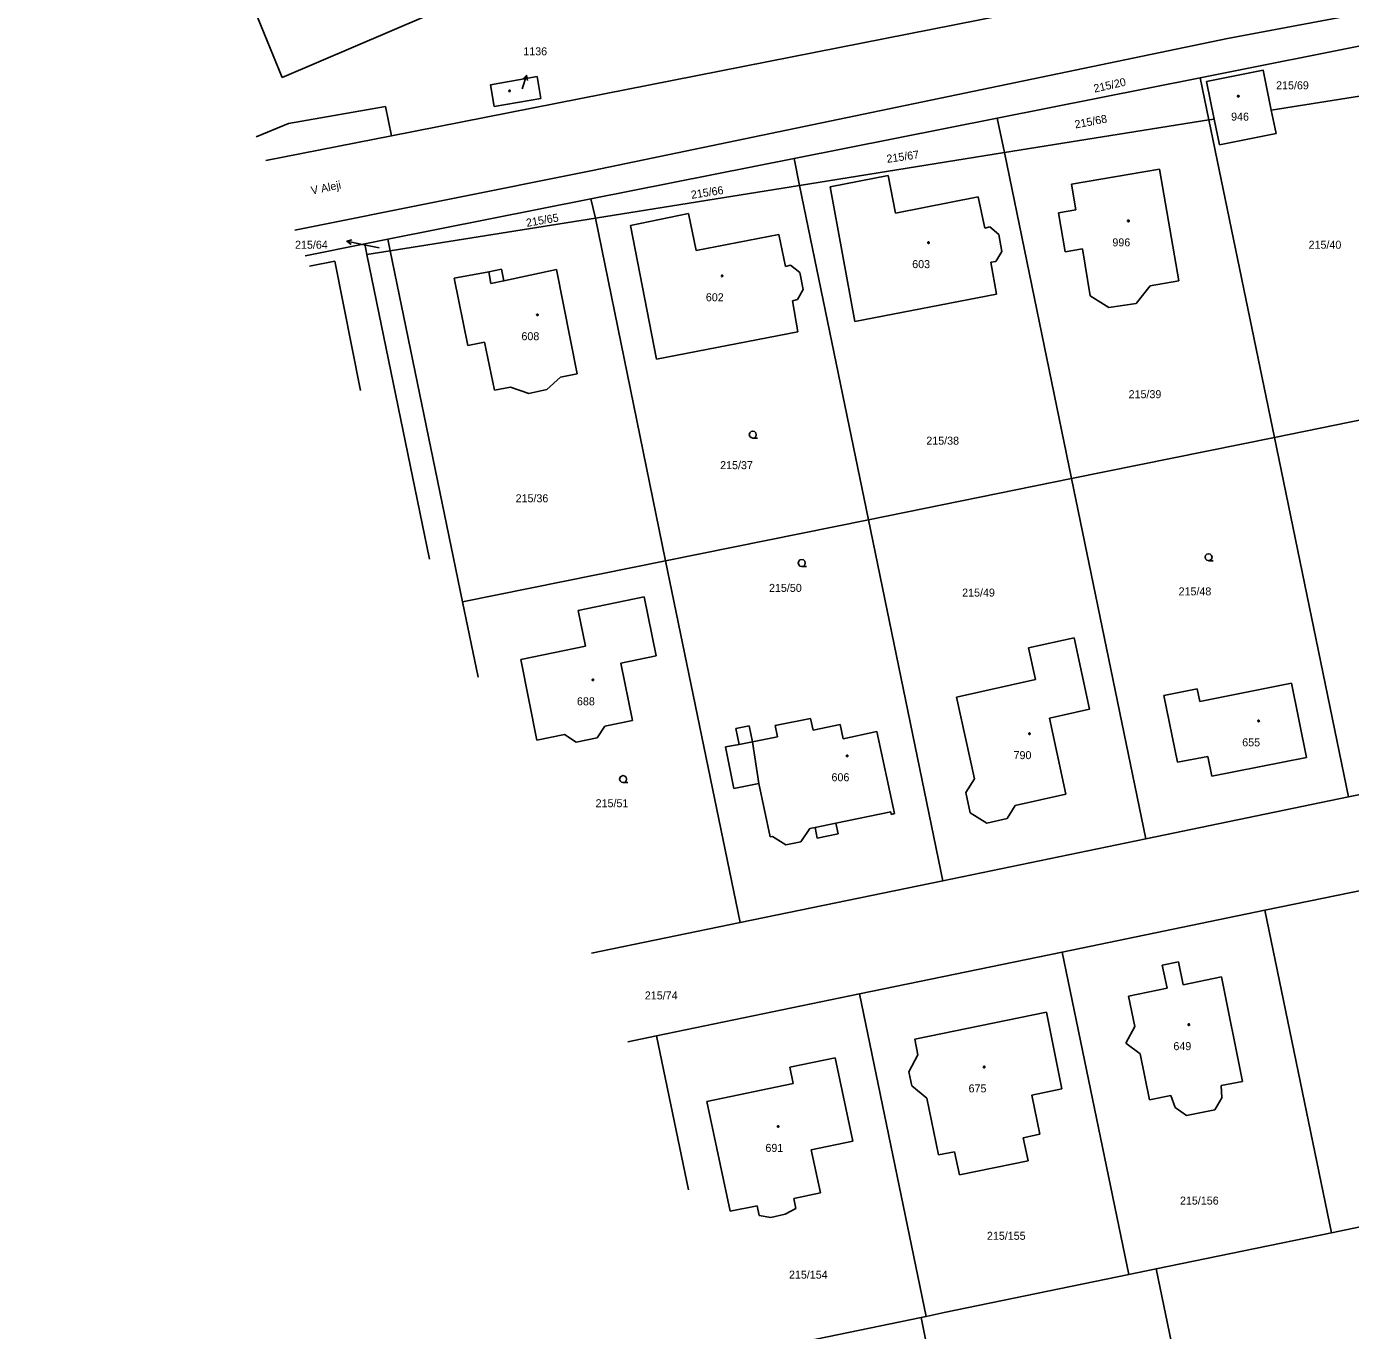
# Model space of a CAD drawing. Extents: x -757994 to -755874, y -1047691 to -1046119.
# Drawn here: x -757810.3 to -757669.7, y -1047577.8 to -1047439.3 of the extents above; entities that cross this region are included whole.
import ezdxf

# ---------------------------------------------------------------- set-up
doc = ezdxf.new("R2010")
doc.units = 0
doc.layers.add('katastrální mapa', color=7, linetype='Continuous')

msp = doc.modelspace()

# ---------------------------------------------------------------- linework, layer by layer
at = {"layer": 'katastrální mapa'}
for p, q in [((-757783.16, -1047444.68), (-757810.32, -1047378.56)), ((-757682.72, -1047440.57), (-757599.86, -1047424.91)), ((-757675.45, -1047431.93), (-757771.54, -1047450.88)), ((-757767.82, -1047438.13), (-757783.16, -1047444.68)), ((-757750.19, -1047454.57), (-757682.72, -1047440.57)), ((-757685.63, -1047444.72), (-757664.05, -1047440.42)), ((-757761.03, -1047445.47), (-757756.06, -1047444.6)), ((-757757.2, -1047444.48), (-757757.65, -1047445.91)), ((-757756.06, -1047444.6), (-757755.68, -1047446.92)), ((-757685.63, -1047444.72), (-757707.2, -1047449.01)), ((-757685.63, -1047444.72), (-757684.71, -1047449.2)), ((-757760.63, -1047447.78), (-757761.03, -1047445.47)), ((-757684.14, -1047449.11), (-757684.95, -1047445.13)), ((-757678.09, -1047448.16), (-757662.94, -1047445.78)), ((-757782.5, -1047449.57), (-757772.19, -1047447.78)), ((-757772.19, -1047447.78), (-757771.54, -1047450.88)), ((-757755.68, -1047446.92), (-757760.63, -1047447.78)), ((-757728.78, -1047453.3), (-757707.2, -1047449.01)), ((-757707.2, -1047449.01), (-757706.44, -1047452.68)), ((-757684.71, -1047449.2), (-757706.44, -1047452.68)), ((-757684.71, -1047449.2), (-757684.14, -1047449.11)), ((-757684.71, -1047449.2), (-757677.75, -1047482.93)), ((-757785.91, -1047450.99), (-757782.5, -1047449.57)), ((-757771.54, -1047450.88), (-757784.88, -1047453.51)), ((-757750.36, -1047457.6), (-757728.78, -1047453.3)), ((-757728.78, -1047453.3), (-757728.19, -1047456.16)), ((-757706.44, -1047452.68), (-757728.19, -1047456.16)), ((-757706.44, -1047452.68), (-757699.32, -1047487.3)), ((-757781.83, -1047460.92), (-757750.19, -1047454.57)), ((-757699.3, -1047456.03), (-757689.94, -1047454.42)), ((-757689.94, -1047454.42), (-757687.9, -1047466.29)), ((-757728.19, -1047456.16), (-757749.88, -1047459.64)), ((-757720.88, -1047491.68), (-757728.19, -1047456.16)), ((-757724.96, -1047456.32), (-757718.77, -1047455.12)), ((-757722.31, -1047470.62), (-757724.96, -1047456.32)), ((-757718.77, -1047455.12), (-757718.01, -1047459.1)), ((-757698.85, -1047458.76), (-757699.3, -1047456.03)), ((-757771.94, -1047461.89), (-757750.36, -1047457.6)), ((-757750.36, -1047457.6), (-757749.88, -1047459.64)), ((-757718.01, -1047459.1), (-757709.22, -1047457.37)), ((-757709.22, -1047457.37), (-757708.53, -1047460.69)), ((-757746.16, -1047460.41), (-757739.98, -1047459.16)), ((-757739.98, -1047459.16), (-757739.18, -1047463.08)), ((-757700.68, -1047459.07), (-757698.85, -1047458.76)), ((-757699.97, -1047463.21), (-757700.68, -1047459.07)), ((-757749.88, -1047459.64), (-757771.68, -1047463.13)), ((-757749.88, -1047459.64), (-757742.44, -1047496.05)), ((-757743.4, -1047474.62), (-757746.16, -1047460.41)), ((-757708.53, -1047460.69), (-757707.97, -1047460.57)), ((-757707.97, -1047460.57), (-757707.01, -1047461.36)), ((-757774.39, -1047462.38), (-757771.94, -1047461.89)), ((-757771.94, -1047461.89), (-757771.68, -1047463.13)), ((-757739.18, -1047463.08), (-757730.38, -1047461.39)), ((-757730.38, -1047461.39), (-757729.7, -1047464.76)), ((-757707.01, -1047461.36), (-757706.7, -1047463.18)), ((-757774.39, -1047462.38), (-757780.72, -1047463.64)), ((-757776.28, -1047462.09), (-757774.81, -1047462.4)), ((-757772.84, -1047462.81), (-757774.81, -1047462.4)), ((-757774.39, -1047462.38), (-757774.15, -1047463.52)), ((-757774.15, -1047463.52), (-757771.68, -1047463.13)), ((-757771.68, -1047463.13), (-757764, -1047500.42)), ((-757706.7, -1047463.18), (-757707.34, -1047464.23)), ((-757698.14, -1047462.91), (-757699.97, -1047463.21)), ((-757697.31, -1047467.9), (-757698.14, -1047462.91)), ((-757780.27, -1047464.74), (-757777.56, -1047464.21)), ((-757777.56, -1047464.21), (-757774.84, -1047477.95)), ((-757767.49, -1047495.89), (-757774.15, -1047463.52)), ((-757729.7, -1047464.76), (-757729.15, -1047464.64)), ((-757729.15, -1047464.64), (-757728.18, -1047465.42)), ((-757707.34, -1047464.23), (-757707.89, -1047464.33)), ((-757707.89, -1047464.33), (-757707.26, -1047467.71)), ((-757761.22, -1047465.33), (-757764.87, -1047466.03)), ((-757764.87, -1047466.03), (-757763.42, -1047473.16)), ((-757759.86, -1047465.07), (-757761.22, -1047465.33)), ((-757761.22, -1047465.33), (-757760.98, -1047466.57)), ((-757759.62, -1047466.31), (-757759.86, -1047465.07)), ((-757754, -1047465.09), (-757759.62, -1047466.31)), ((-757751.81, -1047476.19), (-757754, -1047465.09)), ((-757728.18, -1047465.42), (-757727.82, -1047467.21)), ((-757760.98, -1047466.57), (-757759.62, -1047466.31)), ((-757727.82, -1047467.21), (-757728.4, -1047468.28)), ((-757690.94, -1047466.82), (-757692.43, -1047468.7)), ((-757687.9, -1047466.29), (-757690.94, -1047466.82)), ((-757728.4, -1047468.28), (-757728.96, -1047468.41)), ((-757728.96, -1047468.41), (-757728.37, -1047471.73)), ((-757707.26, -1047467.71), (-757722.31, -1047470.62)), ((-757695.35, -1047469.12), (-757697.31, -1047467.9)), ((-757692.43, -1047468.7), (-757695.35, -1047469.12)), ((-757728.37, -1047471.73), (-757743.4, -1047474.62)), ((-757763.42, -1047473.16), (-757761.65, -1047472.8)), ((-757761.65, -1047472.8), (-757760.61, -1047477.92)), ((-757755.03, -1047477.84), (-757753.58, -1047476.55)), ((-757753.58, -1047476.55), (-757751.81, -1047476.19)), ((-757760.61, -1047477.92), (-757758.89, -1047477.6)), ((-757758.89, -1047477.6), (-757756.96, -1047478.26)), ((-757756.96, -1047478.26), (-757755.03, -1047477.84)), ((-757656.19, -1047478.56), (-757677.75, -1047482.93)), ((-757677.75, -1047482.93), (-757699.32, -1047487.3)), ((-757677.75, -1047482.93), (-757669.87, -1047521.14)), ((-757699.32, -1047487.3), (-757720.88, -1047491.68)), ((-757691.42, -1047525.59), (-757699.32, -1047487.3)), ((-757742.44, -1047496.05), (-757720.88, -1047491.68)), ((-757720.88, -1047491.68), (-757712.96, -1047530.04)), ((-757742.44, -1047496.05), (-757764, -1047500.42)), ((-757734.51, -1047534.49), (-757742.44, -1047496.05)), ((-757751.72, -1047501.33), (-757744.71, -1047499.89)), ((-757744.71, -1047499.89), (-757743.42, -1047506.16)), ((-757764, -1047500.42), (-757762.35, -1047508.4)), ((-757750.93, -1047505.1), (-757751.72, -1047501.33)), ((-757757.82, -1047506.53), (-757750.93, -1047505.1)), ((-757699.02, -1047504.22), (-757703.87, -1047505.29)), ((-757703.87, -1047505.29), (-757703.14, -1047508.65)), ((-757697.38, -1047511.8), (-757699.02, -1047504.22)), ((-757756.1, -1047515.09), (-757757.82, -1047506.53)), ((-757743.42, -1047506.16), (-757747.19, -1047506.93)), ((-757747.19, -1047506.93), (-757745.94, -1047513.01)), ((-757703.14, -1047508.65), (-757711.51, -1047510.53)), ((-757689.51, -1047510.35), (-757685.97, -1047509.64)), ((-757685.97, -1047509.64), (-757685.69, -1047511.01)), ((-757685.69, -1047511.01), (-757675.92, -1047509.05)), ((-757675.92, -1047509.05), (-757674.33, -1047516.94)), ((-757711.51, -1047510.53), (-757709.61, -1047519.22)), ((-757688.05, -1047517.45), (-757689.51, -1047510.35)), ((-757701.66, -1047512.75), (-757697.38, -1047511.8)), ((-757748.87, -1047513.61), (-757749.69, -1047514.85)), ((-757745.94, -1047513.01), (-757748.87, -1047513.61)), ((-757734.95, -1047513.86), (-757733.54, -1047513.57)), ((-757734.6, -1047515.57), (-757734.95, -1047513.86)), ((-757733.54, -1047513.57), (-757733.2, -1047515.29)), ((-757730.79, -1047513.53), (-757727.02, -1047512.8)), ((-757730.54, -1047514.75), (-757730.79, -1047513.53)), ((-757727.02, -1047512.8), (-757726.74, -1047514.05)), ((-757726.74, -1047514.05), (-757723.88, -1047513.44)), ((-757723.88, -1047513.44), (-757723.56, -1047514.95)), ((-757699.91, -1047520.83), (-757701.66, -1047512.75)), ((-757753.18, -1047514.5), (-757756.1, -1047515.09)), ((-757751.94, -1047515.32), (-757753.18, -1047514.5)), ((-757749.69, -1047514.85), (-757751.94, -1047515.32)), ((-757734.6, -1047515.57), (-757733.2, -1047515.29)), ((-757733.2, -1047515.29), (-757730.54, -1047514.75)), ((-757733.2, -1047515.29), (-757732.53, -1047519.71)), ((-757723.56, -1047514.95), (-757719.99, -1047514.18)), ((-757719.99, -1047514.18), (-757718.12, -1047522.89)), ((-757736.05, -1047515.81), (-757734.6, -1047515.57)), ((-757736.05, -1047515.81), (-757735.16, -1047520.23)), ((-757684.84, -1047516.84), (-757688.05, -1047517.45)), ((-757684.39, -1047518.92), (-757684.84, -1047516.84)), ((-757669.87, -1047521.14), (-757648.32, -1047516.69)), ((-757674.33, -1047516.94), (-757684.39, -1047518.92)), ((-757709.61, -1047519.22), (-757710.52, -1047520.66)), ((-757735.16, -1047520.23), (-757732.53, -1047519.71)), ((-757732.53, -1047519.71), (-757731.32, -1047525.39)), ((-757710.52, -1047520.66), (-757710.07, -1047522.83)), ((-757705.28, -1047522.03), (-757699.91, -1047520.83)), ((-757706.14, -1047523.44), (-757705.28, -1047522.03)), ((-757669.87, -1047521.14), (-757691.42, -1047525.59)), ((-757718.51, -1047522.71), (-757724.34, -1047523.92)), ((-757718.45, -1047522.99), (-757718.51, -1047522.71)), ((-757718.12, -1047522.89), (-757718.45, -1047522.99)), ((-757710.07, -1047522.83), (-757708.31, -1047523.92)), ((-757708.31, -1047523.92), (-757706.14, -1047523.44)), ((-757728.05, -1047525.92), (-757727.12, -1047524.5)), ((-757727.12, -1047524.5), (-757726.54, -1047524.38)), ((-757726.54, -1047524.38), (-757724.34, -1047523.92)), ((-757726.54, -1047524.38), (-757726.31, -1047525.5)), ((-757726.31, -1047525.5), (-757724.11, -1047525.04)), ((-757724.11, -1047525.04), (-757724.34, -1047523.92)), ((-757731.32, -1047525.39), (-757731.07, -1047525.35)), ((-757731.07, -1047525.35), (-757729.67, -1047526.24)), ((-757729.67, -1047526.24), (-757728.05, -1047525.92)), ((-757712.96, -1047530.04), (-757691.42, -1047525.59)), ((-757678.75, -1047533.17), (-757657.2, -1047528.72)), ((-757712.96, -1047530.04), (-757734.51, -1047534.49)), ((-757700.29, -1047537.62), (-757678.75, -1047533.17)), ((-757678.75, -1047533.17), (-757671.67, -1047567.44)), ((-757750.31, -1047537.75), (-757734.51, -1047534.49)), ((-757721.84, -1047542.07), (-757700.29, -1047537.62)), ((-757700.29, -1047537.62), (-757693.21, -1047571.89)), ((-757689.67, -1047539.01), (-757687.95, -1047538.65)), ((-757689.16, -1047541.46), (-757689.67, -1047539.01)), ((-757687.95, -1047538.65), (-757687.44, -1047541.1)), ((-757687.44, -1047541.1), (-757683.38, -1047540.25)), ((-757683.38, -1047540.25), (-757681.15, -1047551.38)), ((-757743.38, -1047546.51), (-757721.84, -1047542.07)), ((-757721.84, -1047542.07), (-757714.76, -1047576.34)), ((-757693.24, -1047542.31), (-757689.16, -1047541.46)), ((-757692.59, -1047545.52), (-757693.24, -1047542.31)), ((-757715.96, -1047546.88), (-757701.95, -1047544.02)), ((-757701.95, -1047544.02), (-757700.32, -1047552.16)), ((-757693.52, -1047547.31), (-757692.59, -1047545.52)), ((-757746.45, -1047547.14), (-757743.38, -1047546.51)), ((-757743.38, -1047546.51), (-757740, -1047562.87)), ((-757715.62, -1047548.54), (-757715.96, -1047546.88)), ((-757692, -1047548.44), (-757693.52, -1047547.31)), ((-757729.23, -1047549.85), (-757724.4, -1047548.86)), ((-757724.4, -1047548.86), (-757722.55, -1047557.7)), ((-757716.58, -1047550.35), (-757715.62, -1047548.54)), ((-757691.01, -1047553.33), (-757692, -1047548.44)), ((-757728.88, -1047551.59), (-757729.23, -1047549.85)), ((-757716.27, -1047551.84), (-757716.58, -1047550.35)), ((-757738.04, -1047553.51), (-757728.88, -1047551.59)), ((-757714.68, -1047553.13), (-757716.27, -1047551.84)), ((-757681.15, -1047551.38), (-757683.41, -1047551.81)), ((-757683.41, -1047551.81), (-757683.35, -1047553.12)), ((-757713.45, -1047559.18), (-757714.68, -1047553.13)), ((-757700.32, -1047552.16), (-757703.52, -1047552.81)), ((-757703.52, -1047552.81), (-757702.67, -1047556.98)), ((-757688.76, -1047552.87), (-757691.01, -1047553.33)), ((-757688.3, -1047554.12), (-757688.76, -1047552.87)), ((-757683.35, -1047553.12), (-757684.09, -1047554.38)), ((-757735.56, -1047565.15), (-757738.04, -1047553.51)), ((-757687.08, -1047554.98), (-757688.3, -1047554.12)), ((-757684.09, -1047554.38), (-757687.08, -1047554.98)), ((-757702.67, -1047556.98), (-757704.43, -1047557.34)), ((-757704.43, -1047557.34), (-757703.92, -1047559.81)), ((-757722.55, -1047557.7), (-757726.96, -1047558.62)), ((-757726.96, -1047558.62), (-757725.97, -1047563.19)), ((-757711.72, -1047558.83), (-757713.45, -1047559.18)), ((-757711.21, -1047561.3), (-757711.72, -1047558.83)), ((-757703.92, -1047559.81), (-757711.21, -1047561.3)), ((-757725.97, -1047563.19), (-757728.82, -1047563.81)), ((-757732.7, -1047564.58), (-757735.56, -1047565.15)), ((-757732.5, -1047565.62), (-757732.7, -1047564.58)), ((-757728.82, -1047563.81), (-757728.59, -1047564.86)), ((-757731.23, -1047565.83), (-757732.5, -1047565.62)), ((-757729.74, -1047565.48), (-757731.23, -1047565.83)), ((-757728.59, -1047564.86), (-757729.74, -1047565.48)), ((-757690.32, -1047571.28), (-757671.67, -1047567.44)), ((-757671.67, -1047567.44), (-757667.79, -1047566.64)), ((-757693.21, -1047571.89), (-757690.32, -1047571.28)), ((-757690.32, -1047571.28), (-757683.2, -1047605.55)), ((-757712.84, -1047575.93), (-757693.21, -1047571.89)), ((-757714.76, -1047576.34), (-757712.84, -1047575.93)), ((-757732.94, -1047580.08), (-757715.29, -1047576.44)), ((-757715.29, -1047576.44), (-757714.76, -1047576.34)), ((-757708.16, -1047610.74), (-757715.29, -1047576.44))]:
    msp.add_line(p, q, dxfattribs=at)
for points in [[(-757757.59, -1047444.88), (-757757.2, -1047444.48), (-757757.11, -1047445.03)], [(-757684.95, -1047445.13), (-757678.94, -1047443.92), (-757678.09, -1047448.16)], [(-757678.09, -1047448.16), (-757677.58, -1047450.64), (-757683.58, -1047451.85), (-757684.14, -1047449.11)], [(-757775.84, -1047462.44), (-757776.28, -1047462.09), (-757775.74, -1047461.95)], [(-757733.16, -1047483.01), (-757733.35, -1047482.96), (-757733.49, -1047482.83), (-757733.54, -1047482.64), (-757733.49, -1047482.46), (-757733.35, -1047482.32), (-757733.17, -1047482.27), (-757732.98, -1047482.32), (-757732.85, -1047482.46), (-757732.8, -1047482.65), (-757732.85, -1047482.84), (-757732.98, -1047482.97), (-757733.17, -1047483.02), (-757732.67, -1047483.02)], [(-757684.74, -1047496.03), (-757684.93, -1047495.98), (-757685.07, -1047495.85), (-757685.11, -1047495.66), (-757685.07, -1047495.48), (-757684.93, -1047495.34), (-757684.74, -1047495.29), (-757684.56, -1047495.34), (-757684.43, -1047495.48), (-757684.38, -1047495.67), (-757684.43, -1047495.86), (-757684.56, -1047495.99), (-757684.75, -1047496.04), (-757684.25, -1047496.04)], [(-757727.96, -1047496.65), (-757728.15, -1047496.6), (-757728.28, -1047496.47), (-757728.34, -1047496.28), (-757728.28, -1047496.1), (-757728.15, -1047495.96), (-757727.97, -1047495.91), (-757727.78, -1047495.96), (-757727.65, -1047496.1), (-757727.6, -1047496.29), (-757727.65, -1047496.48), (-757727.78, -1047496.61), (-757727.97, -1047496.66), (-757727.47, -1047496.66)], [(-757746.93, -1047519.61), (-757747.12, -1047519.56), (-757747.26, -1047519.43), (-757747.31, -1047519.24), (-757747.26, -1047519.05), (-757747.12, -1047518.92), (-757746.94, -1047518.87), (-757746.75, -1047518.92), (-757746.61, -1047519.05), (-757746.57, -1047519.24), (-757746.61, -1047519.44), (-757746.75, -1047519.57), (-757746.94, -1047519.62), (-757746.44, -1047519.62)]]:
    msp.add_lwpolyline(points, dxfattribs=at)
for points in [[(-757759.01, -1047446.03), (-757758.96, -1047446.04), (-757758.94, -1047446.09), (-757758.93, -1047446.12), (-757758.94, -1047446.17), (-757758.98, -1047446.2), (-757759.01, -1047446.21), (-757759.05, -1047446.19), (-757759.09, -1047446.16), (-757759.1, -1047446.12), (-757759.09, -1047446.08), (-757759.04, -1047446.04)], [(-757681.58, -1047446.6), (-757681.53, -1047446.61), (-757681.5, -1047446.65), (-757681.49, -1047446.68), (-757681.5, -1047446.73), (-757681.54, -1047446.76), (-757681.58, -1047446.77), (-757681.62, -1047446.75), (-757681.66, -1047446.72), (-757681.67, -1047446.68), (-757681.66, -1047446.64), (-757681.61, -1047446.6)], [(-757693.26, -1047459.86), (-757693.21, -1047459.87), (-757693.19, -1047459.91), (-757693.18, -1047459.94), (-757693.19, -1047459.98), (-757693.23, -1047460.02), (-757693.26, -1047460.02), (-757693.3, -1047460.01), (-757693.34, -1047459.98), (-757693.35, -1047459.94), (-757693.34, -1047459.9), (-757693.29, -1047459.86)], [(-757714.49, -1047462.17), (-757714.44, -1047462.18), (-757714.42, -1047462.22), (-757714.41, -1047462.25), (-757714.42, -1047462.29), (-757714.46, -1047462.33), (-757714.49, -1047462.34), (-757714.53, -1047462.32), (-757714.57, -1047462.29), (-757714.58, -1047462.25), (-757714.57, -1047462.21), (-757714.52, -1047462.17)], [(-757736.42, -1047465.69), (-757736.37, -1047465.7), (-757736.35, -1047465.74), (-757736.34, -1047465.77), (-757736.35, -1047465.82), (-757736.39, -1047465.85), (-757736.42, -1047465.86), (-757736.47, -1047465.84), (-757736.5, -1047465.81), (-757736.51, -1047465.77), (-757736.5, -1047465.73), (-757736.46, -1047465.69)], [(-757756.05, -1047469.83), (-757756, -1047469.84), (-757755.98, -1047469.88), (-757755.97, -1047469.91), (-757755.98, -1047469.96), (-757756.02, -1047469.99), (-757756.05, -1047470), (-757756.1, -1047469.98), (-757756.12, -1047469.95), (-757756.14, -1047469.91), (-757756.12, -1047469.87), (-757756.09, -1047469.83)], [(-757750.15, -1047508.62), (-757750.1, -1047508.62), (-757750.08, -1047508.67), (-757750.07, -1047508.7), (-757750.08, -1047508.74), (-757750.11, -1047508.78), (-757750.15, -1047508.78), (-757750.2, -1047508.77), (-757750.23, -1047508.74), (-757750.24, -1047508.7), (-757750.23, -1047508.66), (-757750.19, -1047508.62)], [(-757679.44, -1047512.98), (-757679.39, -1047512.99), (-757679.36, -1047513.03), (-757679.35, -1047513.06), (-757679.36, -1047513.11), (-757679.41, -1047513.14), (-757679.44, -1047513.15), (-757679.48, -1047513.13), (-757679.51, -1047513.1), (-757679.52, -1047513.06), (-757679.51, -1047513.02), (-757679.47, -1047512.98)], [(-757703.77, -1047514.34), (-757703.72, -1047514.35), (-757703.7, -1047514.39), (-757703.69, -1047514.42), (-757703.7, -1047514.47), (-757703.74, -1047514.5), (-757703.77, -1047514.51), (-757703.82, -1047514.49), (-757703.85, -1047514.46), (-757703.85, -1047514.42), (-757703.85, -1047514.38), (-757703.8, -1047514.34)], [(-757723.13, -1047516.69), (-757723.08, -1047516.7), (-757723.05, -1047516.74), (-757723.04, -1047516.77), (-757723.05, -1047516.82), (-757723.1, -1047516.85), (-757723.13, -1047516.86), (-757723.18, -1047516.84), (-757723.21, -1047516.81), (-757723.22, -1047516.77), (-757723.21, -1047516.73), (-757723.17, -1047516.69)], [(-757686.84, -1047545.25), (-757686.79, -1047545.26), (-757686.76, -1047545.31), (-757686.75, -1047545.34), (-757686.76, -1047545.39), (-757686.8, -1047545.42), (-757686.84, -1047545.43), (-757686.89, -1047545.41), (-757686.92, -1047545.38), (-757686.93, -1047545.34), (-757686.92, -1047545.29), (-757686.88, -1047545.26)], [(-757708.59, -1047549.74), (-757708.54, -1047549.75), (-757708.51, -1047549.8), (-757708.5, -1047549.83), (-757708.51, -1047549.88), (-757708.55, -1047549.91), (-757708.59, -1047549.92), (-757708.64, -1047549.9), (-757708.67, -1047549.87), (-757708.68, -1047549.83), (-757708.67, -1047549.78), (-757708.62, -1047549.75)], [(-757730.48, -1047556.07), (-757730.43, -1047556.08), (-757730.41, -1047556.12), (-757730.4, -1047556.15), (-757730.41, -1047556.2), (-757730.45, -1047556.23), (-757730.48, -1047556.24), (-757730.52, -1047556.22), (-757730.55, -1047556.19), (-757730.57, -1047556.15), (-757730.55, -1047556.11), (-757730.51, -1047556.07)]]:
    msp.add_lwpolyline(points, close=True, dxfattribs=at)

# ---------------------------------------------------------------- texts
for s, height, p in [('1136', 0.85, (-757757.54, -1047442.34)), ('215/69', 0.85, (-757677.57, -1047445.95)), ('1136', 0.05, (-757757.64, -1047445.91)), ('946', 0.85, (-757682.35, -1047449.28)), ('215/64', 0.85, (-757781.79, -1047462.89)), ('996', 0.85, (-757694.96, -1047462.64)), ('215/40', 0.85, (-757674.12, -1047462.89)), ('215/64', 0.05, (-757772.83, -1047462.81)), ('603', 0.85, (-757716.23, -1047464.95)), ('602', 0.85, (-757738.15, -1047468.47)), ('608', 0.85, (-757757.74, -1047472.61)), ('215/39', 0.85, (-757693.24, -1047478.77)), ('215/38', 0.85, (-757714.73, -1047483.71)), ('215/37', 0.85, (-757736.63, -1047486.31)), ('215/36', 0.85, (-757758.36, -1047489.83)), ('215/50', 0.85, (-757731.44, -1047499.35)), ('215/49', 0.85, (-757710.92, -1047499.85)), ('215/48', 0.85, (-757687.93, -1047499.72)), ('688', 0.85, (-757751.84, -1047511.4)), ('655', 0.85, (-757681.17, -1047515.76)), ('790', 0.85, (-757705.46, -1047517.12)), ('606', 0.85, (-757724.8, -1047519.47)), ('215/51', 0.85, (-757749.86, -1047522.23)), ('215/74', 0.85, (-757744.63, -1047542.65)), ('649', 0.85, (-757688.48, -1047548.04)), ('675', 0.85, (-757710.24, -1047552.53)), ('691', 0.85, (-757731.82, -1047558.85)), ('215/156', 0.85, (-757687.78, -1047564.45)), ('215/155', 0.85, (-757708.29, -1047568.19)), ('215/154', 0.85, (-757729.32, -1047572.32))]:
    msp.add_text(s, height=height, dxfattribs=at).set_placement(p)
for s, rotation, p in [('215/20', 12.6051, (-757696.85, -1047446.3)), ('215/68', 10.9435, (-757698.88, -1047450.12)), ('215/67', 8.136, (-757718.89, -1047453.77)), ('V Aleji', 11.6883, (-757780, -1047457.14)), ('215/66', 8.8236, (-757739.66, -1047457.59)), ('215/65', 9.8549, (-757757.16, -1047460.57))]:
    msp.add_text(s, height=0.85, rotation=rotation, dxfattribs=at).set_placement(p)

doc.saveas('drawing.dxf')
